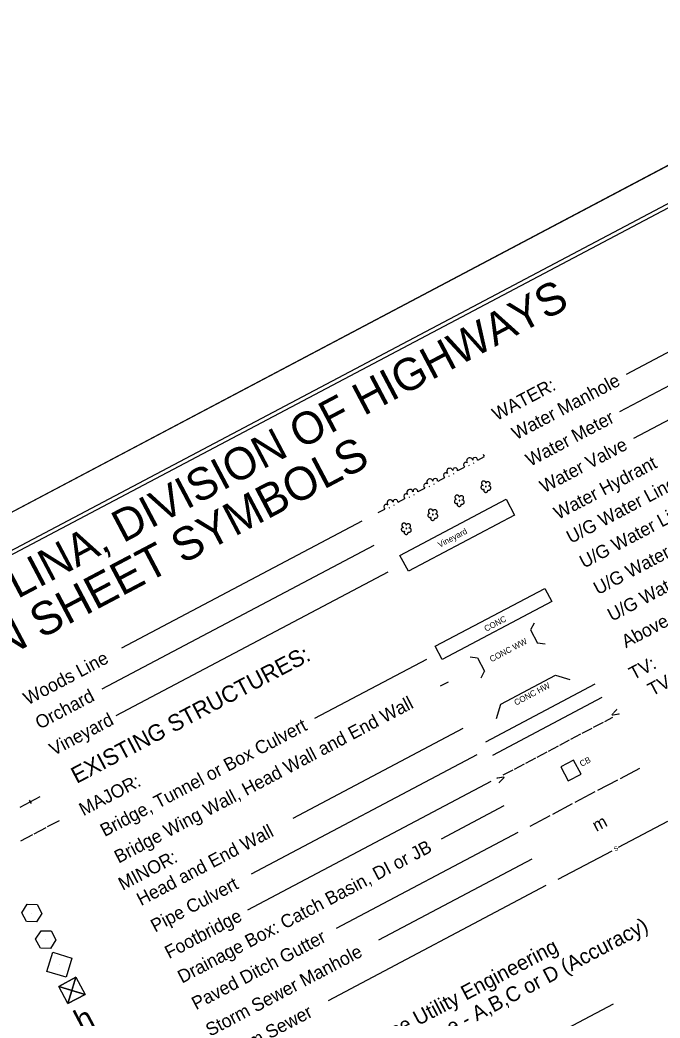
# Model space of a CAD drawing. Extents: x 1487118 to 1489121, y 496367 to 498126.
# Drawn here: x 1487992 to 1488418, y 497462 to 498126 of the extents above; entities that cross this region are included whole.
import ezdxf

# ---------------------------------------------------------------- set-up
doc = ezdxf.new("R2010")
doc.units = 0
for name, color, linetype in [('Sheet Clip Boundary CELL', 7, 'Continuous'), ('Sheet Cutting Line CELL', 7, 'Continuous'), ('Sheet Plot Border Inside CELL', 7, 'Continuous'), ('Sheet Plot Border Outside CELL', 7, 'Continuous'), ('Sheet Symbology CELL', 7, 'Continuous')]:
    doc.layers.add(name, color=color, linetype=linetype)

msp = doc.modelspace()

# ---------------------------------------------------------------- linework, layer by layer
at = {"layer": 'Sheet Clip Boundary CELL'}
for p, q in [((1487999.48, 497531.47), (1487999.48, 497531.47)), ((1488008.8, 497513.81), (1488008.8, 497513.81)), ((1488017.82, 497497), (1488017.82, 497497)), ((1488026.25, 497479.97), (1488026.25, 497479.97))]:
    msp.add_line(p, q, dxfattribs=at)
for points in [[(1488002.59, 497525.59), (1487995.92, 497525.79), (1487992.82, 497531.68), (1487996.37, 497537.35), (1488003.04, 497537.15), (1488006.18, 497531.2), (1488002.59, 497525.59)], [(1488028.95, 497488.72), (1488023.54, 497471.19), (1488026.25, 497479.95), (1488035.01, 497477.25), (1488017.48, 497482.66)], [(1488026.25, 497479.95), (1488028.95, 497488.72), (1488017.48, 497482.66), (1488026.25, 497479.95)], [(1488026.25, 497479.95), (1488023.54, 497471.19), (1488035.01, 497477.25), (1488026.25, 497479.95)]]:
    msp.add_lwpolyline(points, dxfattribs=at)
for points in [[(1488002.06, 497514.07), (1488005.72, 497519.7), (1488012.41, 497519.59), (1488015.47, 497513.6), (1488011.88, 497507.85), (1488005.24, 497508.05)], [(1488009.49, 497492.64), (1488013.43, 497505.42), (1488026.24, 497501.46), (1488022.29, 497488.69)], [(1488017.48, 497482.66), (1488028.95, 497488.72), (1488035.01, 497477.25), (1488023.54, 497471.19)]]:
    msp.add_lwpolyline(points, close=True, dxfattribs=at)
at = {"layer": 'Sheet Cutting Line CELL'}
msp.add_line((1488607.16, 498126.35), (1487118.01, 497340.04), dxfattribs=at)
at = {"layer": 'Sheet Plot Border Inside CELL'}
msp.add_lwpolyline([(1487632.64, 496393.24), (1489106.32, 497171.37), (1488613.66, 498104.39), (1487139.99, 497326.26)], close=True, dxfattribs=at)
at = {"layer": 'Sheet Plot Border Outside CELL'}
msp.add_lwpolyline([(1487631.63, 496367.31), (1489120.78, 497153.62), (1488607.16, 498126.35), (1487118.01, 497340.04)], close=True, dxfattribs=at)
at = {"layer": 'Sheet Symbology CELL'}
for p, q in [((1488539.2, 497966.05), (1488395.6, 497890.23)), ((1488548.54, 497948.37), (1488391.1, 497865.24)), ((1488557.88, 497930.68), (1488400.44, 497847.55)), ((1488290.76, 497829.5), (1488291.2, 497829.73)), ((1488293.86, 497831.13), (1488294.3, 497831.36)), ((1488296.76, 497833.23), (1488301.18, 497835.57)), ((1488277.5, 497822.49), (1488277.94, 497822.73)), ((1488280.59, 497824.13), (1488281.04, 497824.36)), ((1488283.5, 497826.23), (1488287.92, 497828.56)), ((1488264.23, 497815.49), (1488264.68, 497815.72)), ((1488267.33, 497817.12), (1488267.77, 497817.36)), ((1488270.23, 497819.22), (1488274.66, 497821.56)), ((1488254.06, 497810.12), (1488254.51, 497810.35)), ((1488256.97, 497812.22), (1488261.39, 497814.55)), ((1488240.8, 497803.12), (1488241.24, 497803.35)), ((1488243.71, 497805.22), (1488248.13, 497807.55)), ((1488250.97, 497808.48), (1488251.41, 497808.72)), ((1488230.44, 497798.21), (1488234.86, 497800.55)), ((1488237.7, 497801.48), (1488238.15, 497801.71)), ((1488219.48, 497792.42), (1488059.31, 497707.85)), ((1488227.35, 497776.31), (1488046.13, 497680.62)), ((1488236.69, 497758.62), (1488055.47, 497662.93)), ((1488334.21, 497724.57), (1488331.92, 497720.13)), ((1488331.92, 497720.13), (1488336.59, 497711.28)), ((1488341.55, 497710.67), (1488336.59, 497711.28)), ((1488262.53, 497700.45), (1488187.87, 497661.03)), ((1488291.58, 497702.07), (1488296.55, 497701.45)), ((1488296.55, 497701.45), (1488301.22, 497692.61)), ((1488298.93, 497688.16), (1488301.22, 497692.61)), ((1488312.1, 497670.65), (1488348.58, 497689.92)), ((1488348.58, 497689.92), (1488358.14, 497686.96)), ((1488271.87, 497682.76), (1488277.16, 497685.56)), ((1488302.03, 497645.55), (1488374.99, 497684.07)), ((1488306.7, 497636.71), (1488379.66, 497675.23)), ((1488309.15, 497661.09), (1488312.1, 497670.65)), ((1488373.84, 497655.19), (1488380.47, 497658.69)), ((1488381.36, 497659.16), (1488386.66, 497661.96)), ((1488286.81, 497654.47), (1488173.35, 497594.56)), ((1488358.81, 497647.25), (1488365.44, 497650.76)), ((1488366.32, 497651.22), (1488372.95, 497654.73)), ((1488351.29, 497643.29), (1488357.92, 497646.79)), ((1488296.14, 497636.78), (1488145.65, 497557.32)), ((1488336.26, 497635.35), (1488342.89, 497638.85)), ((1488343.77, 497639.32), (1488350.41, 497642.82)), ((1488321.22, 497627.41), (1488327.86, 497630.91)), ((1488328.74, 497631.38), (1488335.37, 497634.88)), ((1488313.71, 497623.44), (1488320.34, 497626.94)), ((1488391.79, 497621.2), (1488404.61, 497627.97)), ((1488305.48, 497619.1), (1488143.24, 497533.43)), ((1488376.75, 497613.27), (1488390.02, 497620.27)), ((1488361.72, 497605.33), (1488374.98, 497612.33)), ((1487991.79, 497602.04), (1488005.06, 497609.04)), ((1487997.84, 497606.65), (1487999.01, 497604.43)), ((1488346.69, 497597.39), (1488359.95, 497604.39)), ((1488314.09, 497602.8), (1488272.35, 497580.76)), ((1488331.65, 497589.45), (1488344.92, 497596.46)), ((1488009.98, 497589.02), (1488017.93, 497593.22)), ((1488390.59, 497575.34), (1488423.29, 497592.6)), ((1487992.29, 497579.68), (1488000.25, 497583.89)), ((1488001.13, 497584.35), (1488009.09, 497588.55)), ((1488323.43, 497585.11), (1488202.33, 497521.16)), ((1488350.33, 497554.08), (1488386.17, 497573)), ((1488332.77, 497567.42), (1488230.48, 497513.41)), ((1488342.11, 497549.74), (1488196.91, 497473.07)), ((1488386.91, 497470.85), (1488264.26, 497406.09))]:
    msp.add_line(p, q, dxfattribs=at)
for points in [[(1488603.8, 498096.3), (1487277.36, 497395.91), (1487767.16, 496468.3), (1489093.6, 497168.69)], [(1488357.02, 497619.45), (1488365.52, 497623.94), (1488360.55, 497633.35), (1488352.05, 497628.86)]]:
    msp.add_lwpolyline(points, close=True, dxfattribs=at)
for points in [[(1488302.09, 497817.75), (1488302.08, 497818.09), (1488301.99, 497818.38), (1488301.8, 497818.62), (1488301.62, 497818.86), (1488301.37, 497819.01), (1488301.12, 497819.16), (1488300.81, 497819.22), (1488300.52, 497819.24), (1488300.16, 497819.16), (1488299.94, 497819.05), (1488299.7, 497818.86), (1488299.48, 497818.63), (1488299.33, 497818.38), (1488299.2, 497818.09), (1488299.21, 497817.75), (1488299.24, 497817.49), (1488299.33, 497817.2), (1488299.47, 497816.93), (1488299.66, 497816.69), (1488299.9, 497816.54), (1488300.22, 497816.37), (1488299.93, 497816.38), (1488299.64, 497816.29), (1488299.38, 497816.15), (1488299.2, 497815.94), (1488299.03, 497815.74), (1488298.9, 497815.44), (1488298.82, 497815.17), (1488298.8, 497814.88), (1488298.87, 497814.64), (1488298.99, 497814.31), (1488299.15, 497814.11), (1488299.36, 497813.93), (1488299.65, 497813.81), (1488299.88, 497813.7), (1488300.17, 497813.68), (1488300.5, 497813.69), (1488300.75, 497813.76), (1488301.01, 497813.9), (1488300.84, 497813.7), (1488300.71, 497813.4), (1488300.67, 497813.16), (1488300.72, 497812.84), (1488300.78, 497812.53), (1488300.89, 497812.31), (1488301.08, 497812.07), (1488301.33, 497811.92), (1488301.58, 497811.77), (1488301.85, 497811.68), (1488302.14, 497811.67), (1488302.41, 497811.7), (1488302.67, 497811.84), (1488302.94, 497811.98), (1488303.13, 497812.14), (1488303.26, 497812.43), (1488303.41, 497812.68), (1488303.42, 497813.2)], [(1488302.16, 497815.81), (1488302.03, 497815.74), (1488301.96, 497815.65), (1488301.89, 497815.55), (1488301.96, 497815.42), (1488302.01, 497815.33), (1488302.15, 497815.29), (1488302.28, 497815.36), (1488302.37, 497815.41), (1488302.41, 497815.54), (1488302.38, 497815.7), (1488302.29, 497815.76), (1488302.16, 497815.81)], [(1488303.42, 497813.2), (1488304.12, 497813.17), (1488304.43, 497813.22), (1488304.72, 497813.31), (1488304.96, 497813.5), (1488305.13, 497813.7), (1488305.29, 497813.95), (1488305.41, 497814.25), (1488305.43, 497814.54), (1488305.4, 497814.81), (1488305.35, 497815.12), (1488305.16, 497815.36), (1488304.98, 497815.6), (1488304.66, 497815.77), (1488304.44, 497815.88), (1488304.15, 497815.9), (1488303.81, 497815.89), (1488304.1, 497815.98), (1488304.41, 497816.15), (1488304.58, 497816.35), (1488304.78, 497816.63), (1488304.93, 497816.87), (1488304.99, 497817.19), (1488304.98, 497817.52), (1488304.89, 497817.81), (1488304.79, 497818.1), (1488304.61, 497818.34), (1488304.38, 497818.56), (1488304.08, 497818.69), (1488303.75, 497818.79), (1488303.46, 497818.81), (1488303.14, 497818.76), (1488302.85, 497818.66), (1488302.59, 497818.52), (1488302.37, 497818.29), (1488302.22, 497818.04), (1488302.09, 497817.75)], [(1488284.41, 497808.41), (1488284.4, 497808.75), (1488284.3, 497809.04), (1488284.12, 497809.28), (1488283.93, 497809.52), (1488283.69, 497809.67), (1488283.44, 497809.82), (1488283.12, 497809.88), (1488282.83, 497809.9), (1488282.47, 497809.82), (1488282.25, 497809.71), (1488282.01, 497809.52), (1488281.79, 497809.29), (1488281.64, 497809.04), (1488281.51, 497808.75), (1488281.52, 497808.42), (1488281.55, 497808.15), (1488281.65, 497807.86), (1488281.79, 497807.59), (1488281.97, 497807.35), (1488282.22, 497807.2), (1488282.54, 497807.03), (1488282.24, 497807.05), (1488281.96, 497806.95), (1488281.69, 497806.81), (1488281.52, 497806.6), (1488281.34, 497806.4), (1488281.21, 497806.11), (1488281.13, 497805.83), (1488281.12, 497805.54), (1488281.19, 497805.3), (1488281.31, 497804.97), (1488281.47, 497804.77), (1488281.67, 497804.59), (1488281.97, 497804.47), (1488282.19, 497804.36), (1488282.48, 497804.34), (1488282.82, 497804.35), (1488283.06, 497804.42), (1488283.33, 497804.56), (1488283.15, 497804.36), (1488283.03, 497804.07), (1488282.99, 497803.82), (1488283.04, 497803.51), (1488283.09, 497803.19), (1488283.21, 497802.97), (1488283.39, 497802.73), (1488283.64, 497802.58), (1488283.89, 497802.43), (1488284.16, 497802.35), (1488284.45, 497802.33), (1488284.72, 497802.36), (1488284.98, 497802.5), (1488285.25, 497802.64), (1488285.45, 497802.8), (1488285.58, 497803.09), (1488285.73, 497803.34), (1488285.74, 497803.86)], [(1488285.74, 497803.86), (1488286.43, 497803.83), (1488286.74, 497803.88), (1488287.03, 497803.98), (1488287.27, 497804.16), (1488287.45, 497804.36), (1488287.6, 497804.61), (1488287.73, 497804.91), (1488287.74, 497805.2), (1488287.71, 497805.47), (1488287.66, 497805.78), (1488287.48, 497806.02), (1488287.29, 497806.26), (1488286.98, 497806.43), (1488286.75, 497806.54), (1488286.46, 497806.56), (1488286.13, 497806.55), (1488286.41, 497806.65), (1488286.72, 497806.81), (1488286.9, 497807.01), (1488287.09, 497807.29), (1488287.24, 497807.54), (1488287.3, 497807.85), (1488287.3, 497808.19), (1488287.2, 497808.47), (1488287.1, 497808.76), (1488286.92, 497809.01), (1488286.69, 497809.22), (1488286.4, 497809.35), (1488286.06, 497809.46), (1488285.77, 497809.47), (1488285.46, 497809.42), (1488285.17, 497809.32), (1488284.9, 497809.18), (1488284.69, 497808.96), (1488284.53, 497808.71), (1488284.41, 497808.41)], [(1488244.85, 497769.71), (1488315.59, 497807.07), (1488321.2, 497796.46), (1488250.45, 497759.1), (1488244.85, 497769.71)], [(1488284.47, 497806.47), (1488284.34, 497806.4), (1488284.27, 497806.31), (1488284.21, 497806.22), (1488284.28, 497806.08), (1488284.33, 497806), (1488284.46, 497805.95), (1488284.59, 497806.02), (1488284.68, 497806.07), (1488284.72, 497806.21), (1488284.7, 497806.36), (1488284.61, 497806.43), (1488284.47, 497806.47)], [(1488266.72, 497799.07), (1488266.71, 497799.41), (1488266.62, 497799.7), (1488266.43, 497799.94), (1488266.25, 497800.18), (1488266, 497800.33), (1488265.75, 497800.48), (1488265.44, 497800.54), (1488265.14, 497800.56), (1488264.79, 497800.48), (1488264.57, 497800.37), (1488264.33, 497800.18), (1488264.11, 497799.96), (1488263.96, 497799.71), (1488263.83, 497799.41), (1488263.84, 497799.08), (1488263.86, 497798.81), (1488263.96, 497798.52), (1488264.1, 497798.26), (1488264.28, 497798.01), (1488264.53, 497797.86), (1488264.85, 497797.69), (1488264.56, 497797.71), (1488264.27, 497797.61), (1488264, 497797.47), (1488263.83, 497797.27), (1488263.66, 497797.06), (1488263.53, 497796.77), (1488263.45, 497796.5), (1488263.43, 497796.21), (1488263.5, 497795.96), (1488263.62, 497795.63), (1488263.78, 497795.43), (1488263.99, 497795.26), (1488264.28, 497795.13), (1488264.51, 497795.02), (1488264.8, 497795.01), (1488265.13, 497795.01), (1488265.38, 497795.09), (1488265.64, 497795.23), (1488265.47, 497795.02), (1488265.34, 497794.73), (1488265.3, 497794.48), (1488265.35, 497794.17), (1488265.4, 497793.86), (1488265.52, 497793.63), (1488265.71, 497793.39), (1488265.96, 497793.24), (1488266.2, 497793.09), (1488266.47, 497793.01), (1488266.77, 497792.99), (1488267.03, 497793.02), (1488267.3, 497793.16), (1488267.56, 497793.3), (1488267.76, 497793.46), (1488267.89, 497793.75), (1488268.04, 497794), (1488268.05, 497794.52)], [(1488266.79, 497797.13), (1488266.65, 497797.06), (1488266.59, 497796.97), (1488266.52, 497796.88), (1488266.59, 497796.75), (1488266.64, 497796.66), (1488266.77, 497796.61), (1488266.91, 497796.68), (1488267, 497796.73), (1488267.04, 497796.87), (1488267.01, 497797.02), (1488266.92, 497797.09), (1488266.79, 497797.13)], [(1488268.05, 497794.52), (1488268.75, 497794.49), (1488269.06, 497794.54), (1488269.35, 497794.64), (1488269.59, 497794.82), (1488269.76, 497795.03), (1488269.91, 497795.28), (1488270.04, 497795.57), (1488270.06, 497795.86), (1488270.03, 497796.13), (1488269.98, 497796.44), (1488269.79, 497796.68), (1488269.61, 497796.92), (1488269.29, 497797.1), (1488269.07, 497797.2), (1488268.77, 497797.22), (1488268.44, 497797.21), (1488268.73, 497797.31), (1488269.04, 497797.47), (1488269.21, 497797.68), (1488269.41, 497797.95), (1488269.56, 497798.2), (1488269.62, 497798.51), (1488269.61, 497798.85), (1488269.51, 497799.14), (1488269.42, 497799.42), (1488269.23, 497799.67), (1488269.01, 497799.89), (1488268.71, 497800.01), (1488268.37, 497800.12), (1488268.08, 497800.13), (1488267.77, 497800.08), (1488267.48, 497799.99), (1488267.22, 497799.85), (1488267, 497799.62), (1488266.85, 497799.37), (1488266.72, 497799.07)], [(1488249.03, 497789.74), (1488249.03, 497790.07), (1488248.93, 497790.36), (1488248.75, 497790.6), (1488248.56, 497790.84), (1488248.31, 497790.99), (1488248.06, 497791.15), (1488247.75, 497791.21), (1488247.46, 497791.22), (1488247.1, 497791.15), (1488246.88, 497791.03), (1488246.64, 497790.85), (1488246.42, 497790.62), (1488246.27, 497790.37), (1488246.14, 497790.07), (1488246.15, 497789.74), (1488246.18, 497789.47), (1488246.27, 497789.18), (1488246.41, 497788.92), (1488246.6, 497788.67), (1488246.85, 497788.52), (1488247.16, 497788.35), (1488246.87, 497788.37), (1488246.58, 497788.27), (1488246.32, 497788.13), (1488246.14, 497787.93), (1488245.97, 497787.72), (1488245.84, 497787.43), (1488245.76, 497787.16), (1488245.74, 497786.87), (1488245.82, 497786.62), (1488245.93, 497786.29), (1488246.1, 497786.09), (1488246.3, 497785.92), (1488246.59, 497785.79), (1488246.82, 497785.68), (1488247.11, 497785.67), (1488247.45, 497785.67), (1488247.69, 497785.75), (1488247.96, 497785.89), (1488247.78, 497785.68), (1488247.65, 497785.39), (1488247.62, 497785.14), (1488247.67, 497784.83), (1488247.72, 497784.52), (1488247.84, 497784.3), (1488248.02, 497784.05), (1488248.27, 497783.9), (1488248.52, 497783.75), (1488248.79, 497783.67), (1488249.08, 497783.65), (1488249.35, 497783.68), (1488249.61, 497783.82), (1488249.88, 497783.96), (1488250.08, 497784.12), (1488250.2, 497784.42), (1488250.35, 497784.67), (1488250.37, 497785.18)], [(1488250.37, 497785.18), (1488251.06, 497785.15), (1488251.37, 497785.2), (1488251.66, 497785.3), (1488251.9, 497785.48), (1488252.08, 497785.69), (1488252.23, 497785.94), (1488252.36, 497786.23), (1488252.37, 497786.52), (1488252.34, 497786.79), (1488252.29, 497787.1), (1488252.11, 497787.34), (1488251.92, 497787.59), (1488251.61, 497787.76), (1488251.38, 497787.86), (1488251.09, 497787.88), (1488250.75, 497787.87), (1488251.04, 497787.97), (1488251.35, 497788.13), (1488251.53, 497788.34), (1488251.72, 497788.61), (1488251.87, 497788.86), (1488251.93, 497789.17), (1488251.92, 497789.51), (1488251.83, 497789.8), (1488251.73, 497790.09), (1488251.55, 497790.33), (1488251.32, 497790.55), (1488251.03, 497790.67), (1488250.69, 497790.78), (1488250.4, 497790.79), (1488250.09, 497790.74), (1488249.8, 497790.65), (1488249.53, 497790.51), (1488249.31, 497790.28), (1488249.16, 497790.03), (1488249.03, 497789.74)], [(1488249.1, 497787.79), (1488248.97, 497787.72), (1488248.9, 497787.63), (1488248.84, 497787.54), (1488248.91, 497787.41), (1488248.95, 497787.32), (1488249.09, 497787.28), (1488249.22, 497787.35), (1488249.31, 497787.39), (1488249.35, 497787.53), (1488249.33, 497787.68), (1488249.24, 497787.75), (1488249.1, 497787.79)], [(1488268.42, 497709.21), (1488341.37, 497747.73), (1488346.04, 497738.89), (1488273.09, 497700.37), (1488268.42, 497709.21)]]:
    msp.add_lwpolyline(points, dxfattribs=at)
for centre, radius, start, end in [((1488301.99, 497837.14), 1.58, 184.08611, 231.58408), ((1488288.73, 497830.13), 1.58, 46.27004, 247.06661), ((1488291.35, 497832.65), 2.06, 13.79885, 221.87134), ((1488294.92, 497833.4), 1.58, 348.60357, 189.40014), ((1488275.46, 497823.13), 1.58, 46.27004, 247.06661), ((1488278.09, 497825.65), 2.06, 13.79885, 221.87134), ((1488281.65, 497826.4), 1.58, 348.60357, 189.40014), ((1488262.2, 497816.13), 1.58, 46.27004, 247.06661), ((1488264.83, 497818.65), 2.06, 13.79885, 221.87134), ((1488268.39, 497819.4), 1.58, 348.60357, 189.40014), ((1488248.93, 497809.12), 1.58, 46.27004, 247.06661), ((1488251.56, 497811.64), 2.06, 13.79885, 221.87134), ((1488255.12, 497812.39), 1.58, 348.60357, 189.40014), ((1488235.67, 497802.12), 1.58, 46.27004, 247.06661), ((1488238.3, 497804.64), 2.06, 13.79885, 221.87134), ((1488241.86, 497805.39), 1.58, 348.60357, 189.40014)]:
    msp.add_arc(centre, radius, start, end, dxfattribs=at)

# ---------------------------------------------------------------- texts
for s, height, rotation, p in [('STATE OF NORTH CAROLINA, DIVISION OF HIGHWAYS', 21.419, 27.83509, (1487688.84, 497581.56)), ('Water Manhole', 8.75, 27.83509, (1488322.28, 497846.38)), ('WATER:', 8.75, 27.83509, (1488309.24, 497859.15)), ('U/G Water Line Test Hole (SUE - LOS A)*', 8.75, 27.83509, (1488358.74, 497777.33)), ('Water Meter', 8.75, 27.83509, (1488331.62, 497828.7)), ('CONVENTIONAL  PLAN SHEET SYMBOLS', 22.0323, 27.83509, (1487710.45, 497558.05)), ('Water Valve', 8.75, 27.83509, (1488340.96, 497811.01)), ('U/G Water Line (SUE - LOS B)*', 8.75, 27.83509, (1488367.45, 497760.84)), ('Water Hydrant', 8.75, 27.83509, (1488350.3, 497793.33)), ('U/G Water Line (SUE - LOS C)*', 8.75, 27.83509, (1488376.79, 497743.16)), ('U/G Water Line (SUE - LOS D)*', 8.75, 27.83509, (1488386.12, 497725.47)), ('Vineyard', 4, 27.83511, (1488271.42, 497774.7)), ('Above Ground Water Line', 8.75, 27.83509, (1488395.46, 497707.79)), ('CONC', 4, 27.83509, (1488302.31, 497718.78)), ('CONC WW', 4, 27.83511, (1488305.9, 497698.47)), ('TV Pedestal', 8.75, 27.83509, (1488412.9, 497675.78)), ('Woods Line', 8.75, 27.83509, (1487996.84, 497669.75)), ('EXISTING STRUCTURES:', 11, 27.83509, (1488029.36, 497617.42)), ('TV:', 8.75, 27.83509, (1488400.42, 497686.47)), ('CONC HW', 4, 27.83509, (1488322.2, 497669.58)), ('Orchard', 8.75, 27.83509, (1488004.71, 497653.63)), ('Bridge Wing Wall, Head Wall and End Wall', 8.75, 27.83509, (1488057.37, 497564.36)), ('Vineyard', 8.75, 27.83509, (1488014.05, 497635.95)), ('v', 6.6, 298.07595, (1488384.9, 497665.26)), ('Bridge, Tunnel or Box Culvert', 8.75, 27.83509, (1488048.03, 497582.05)), ('CB', 4, 27.83509, (1488365.92, 497628.83)), ('MAJOR:', 8.75, 27.83509, (1488033.89, 497595.93)), ('v', 6.6, 117.59424, (1488315.44, 497620.13)), ('Head and End Wall', 8.75, 27.83509, (1488072.31, 497536.07)), ('m', 8.25, 27.83509, (1488375.75, 497585.45)), ('Drainage Box: Catch Basin, DI or JB', 8.75, 27.83509, (1488099.6, 497484.41)), ('MINOR:', 8.75, 27.83509, (1488060.09, 497546.3)), ('S', 3, 27.83509, (1488388.28, 497572.42)), ('Pipe Culvert', 8.75, 27.83509, (1488081.64, 497518.39)), ('Footbridge', 8.75, 27.83509, (1488090.99, 497500.71)), ('LOS - Level of Service - A,B,C or D (Accuracy) ', 9.9, 27.83509, (1488168.55, 497391.93)), ('Paved Ditch Gutter', 8.75, 27.83509, (1488108.95, 497466.71)), ('* SUE - Subsurface Utility Engineering', 9.9, 27.83509, (1488152.2, 497400.91)), ('Storm Sewer Manhole', 8.75, 27.83509, (1488118.29, 497449.03)), ('h', 15, 27.83509, (1488032.86, 497451.6)), ('Storm Sewer', 8.75, 27.83509, (1488127.62, 497431.34))]:
    msp.add_text(s, height=height, rotation=rotation, dxfattribs=at).set_placement(p)

doc.saveas('drawing.dxf')
